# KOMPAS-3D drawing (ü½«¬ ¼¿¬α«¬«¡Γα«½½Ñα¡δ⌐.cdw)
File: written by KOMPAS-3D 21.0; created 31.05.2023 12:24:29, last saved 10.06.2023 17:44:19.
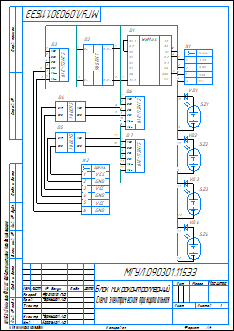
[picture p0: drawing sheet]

Sheet 1: A4, portrait

Document properties: Полное имя файла: C:\Artanis\Учеба\Чертежи\Блок микроконтроллерный.cdw

Title block, sheet 1: Наименование: Блок микроконтроллерный / Схема электрическая принципиальная; designation: МГУЛ.090301.115ЭЗ; Количество листов документа: 1; Форматы листов документа: A4; stored path: C:\Artanis\Учеба\Чертежи\Основной.cdw; Разработал: Фролова П.В.; Проверил: Чернышов А.В.; Н. контр.: Чернышов А.В.; Утвердил: Корольков А.В.

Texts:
  WeMos
  RST
  GND
  CJMCU-219
  VCC
  SCL
  SDA
  Vin+
  Vin-
  LM2596
  In+
  In-
  Out+
  Out-
  CH3791
  BAT
  VD1
  VD2
  VD3
  VD4
  SZ1
  SZ2
  SZ3
  SZ4
  Цепь
  Стили документа
Dimensions and other numbers on the sheet: 3V3; 1; 2; 3; 4; 5; 6; 7; 8; 9; 10; 11; 12; 13; 3,3B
